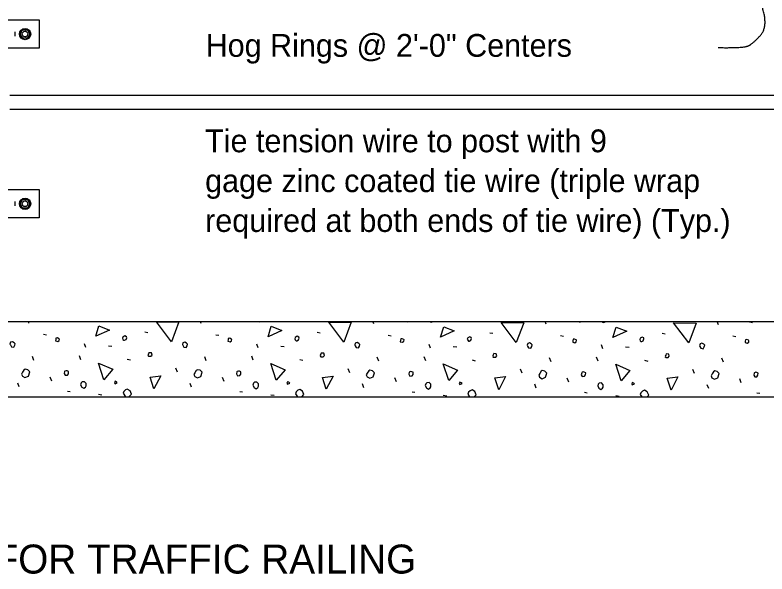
# Model space of a CAD drawing. Extents: x 0 to 72.1, y -7 to 30.
# Drawn here: x 12.41 to 19.06, y 13.96 to 18.9 of the extents above; entities that cross this region are included whole.
import ezdxf

# ---------------------------------------------------------------- set-up
doc = ezdxf.new("R2010")
doc.units = 0
for name, color, linetype in [('AdhocPoint_dp', 7, 'Continuous'), ('Border', 7, 'Continuous'), ('PlotBorder_dp', 7, 'Continuous'), ('TextMisc', 7, 'Continuous'), ('TextStructures', 7, 'Continuous')]:
    doc.layers.add(name, color=color, linetype=linetype)

msp = doc.modelspace()

# ---------------------------------------------------------------- linework, layer by layer
at = {"layer": 'AdhocPoint_dp'}
for p, q in [((12.5379, 16.1758), (12.5327, 16.1899)), ((14.0617, 16.1723), (14.0552, 16.1899)), ((15.5855, 16.1687), (15.5777, 16.1899)), ((15.8807, 16.1899), (15.8878, 16.1882)), ((17.1093, 16.1652), (17.1002, 16.1899)), ((17.3904, 16.1899), (17.4116, 16.1846)), ((18.6332, 16.1617), (18.6227, 16.1899)), ((18.9072, 16.1882), (18.9354, 16.1811)), ((13.5632, 16.098), (13.5897, 16.0927)), ((15.087, 16.0945), (15.1135, 16.0892)), ((16.6108, 16.0909), (16.6373, 16.0856)), ((18.1346, 16.0874), (18.1612, 16.0821)), ((12.6652, 16.0768), (12.6917, 16.0715)), ((14.189, 16.0733), (14.2155, 16.068)), ((15.7128, 16.0697), (15.7393, 16.0644)), ((17.2366, 16.0662), (17.2631, 16.0609)), ((18.7604, 16.0627), (18.787, 16.0574)), ((13.0399, 15.9601), (13.0276, 15.9937)), ((13.2397, 15.976), (13.2715, 15.9725)), ((14.5638, 15.9566), (14.5514, 15.9902)), ((14.7635, 15.9725), (14.7953, 15.969)), ((16.0876, 15.9531), (16.0752, 15.9866)), ((16.2873, 15.969), (16.3191, 15.9654)), ((17.6114, 15.9495), (17.599, 15.9831)), ((17.8111, 15.9654), (17.843, 15.9619)), ((12.5821, 15.8452), (12.5679, 15.8806)), ((12.9975, 15.8505), (12.9834, 15.8859)), ((13.4076, 15.8576), (13.4359, 15.8505)), ((14.1059, 15.8417), (14.0918, 15.877)), ((14.5213, 15.847), (14.5072, 15.8823)), ((14.9315, 15.8541), (14.9597, 15.847)), ((15.6297, 15.8381), (15.6156, 15.8735)), ((16.0451, 15.8435), (16.031, 15.8788)), ((16.4553, 15.8505), (16.4835, 15.8435)), ((17.1535, 15.8346), (17.1394, 15.87)), ((17.569, 15.8399), (17.5548, 15.8753)), ((17.9791, 15.847), (18.0074, 15.8399)), ((18.6773, 15.8311), (18.6632, 15.8664)), ((13.8496, 15.7409), (13.8354, 15.7763)), ((15.3734, 15.7374), (15.3592, 15.7727)), ((16.8972, 15.7339), (16.8831, 15.7692)), ((18.421, 15.7303), (18.4069, 15.7657)), ((12.7394, 15.6631), (12.7253, 15.6985)), ((14.2632, 15.6596), (14.2491, 15.695)), ((15.787, 15.6561), (15.7729, 15.6914)), ((17.3109, 15.6525), (17.2967, 15.6879)), ((12.4513, 15.6119), (12.4389, 15.6455)), ((13.9751, 15.6083), (13.9627, 15.6419)), ((15.4989, 15.6048), (15.4865, 15.6384)), ((17.0227, 15.6013), (17.0103, 15.6349)), ((18.5465, 15.5977), (18.5342, 15.6313)), ((18.8347, 15.649), (18.8205, 15.6844)), ((12.8773, 15.5748), (12.9021, 15.5712)), ((14.4011, 15.5712), (14.4259, 15.5677)), ((15.9249, 15.5677), (15.9497, 15.5641)), ((17.4488, 15.5641), (17.4735, 15.5606)), ((18.9726, 15.5606), (18.9973, 15.5571)), ((13.1531, 15.5465), (13.1831, 15.5412)), ((14.6769, 15.5429), (14.7069, 15.5376)), ((16.2007, 15.5394), (16.2308, 15.5341)), ((17.7245, 15.5359), (17.7546, 15.5306))]:
    msp.add_line(p, q, dxfattribs=at)
for points in [[(13.7983, 16.0114), (13.664, 16.1882), (13.8637, 16.1864), (13.7983, 16.0114)], [(14.5602, 16.1899), (14.5726, 16.1882), (14.5767, 16.1899)], [(15.3221, 16.0079), (15.1878, 16.1846), (15.3875, 16.1829), (15.3221, 16.0079)], [(16.0805, 16.1899), (16.084, 16.1864)], [(16.084, 16.1864), (16.0964, 16.1846), (16.1088, 16.1899)], [(16.8459, 16.0043), (16.7116, 16.1811), (16.9113, 16.1793), (16.8459, 16.0043)], [(17.6008, 16.1899), (17.6078, 16.1829)], [(17.6078, 16.1829), (17.6202, 16.1811), (17.6326, 16.1864), (17.6338, 16.1899)], [(18.3698, 16.0008), (18.2354, 16.1776), (18.4352, 16.1758), (18.3698, 16.0008)], [(13.1283, 16.0591), (13.1566, 16.151), (13.2503, 16.1139), (13.1283, 16.0591)], [(14.6521, 16.0556), (14.6804, 16.1475), (14.7741, 16.1104), (14.6521, 16.0556)], [(16.176, 16.052), (16.2042, 16.144), (16.2979, 16.1068), (16.176, 16.052)], [(17.6998, 16.0485), (17.7281, 16.1404), (17.8217, 16.1033), (17.6998, 16.0485)], [(12.773, 16.0185), (12.7925, 16.0132), (12.8048, 16.022), (12.8066, 16.0344), (12.8031, 16.0379), (12.7889, 16.045), (12.7765, 16.0432), (12.7748, 16.0308), (12.773, 16.0185)], [(13.3758, 16.0238), (13.3829, 16.0238), (13.397, 16.0308), (13.4023, 16.0467), (13.4006, 16.0556), (13.3864, 16.0627), (13.3687, 16.052), (13.3652, 16.0414), (13.3687, 16.0308), (13.3758, 16.0238)], [(14.2968, 16.0149), (14.3163, 16.0096), (14.3286, 16.0185), (14.3304, 16.0308), (14.3269, 16.0344), (14.3127, 16.0414), (14.3004, 16.0397), (14.2986, 16.0273), (14.2968, 16.0149)], [(14.8996, 16.0202), (14.9067, 16.0202), (14.9208, 16.0273), (14.9261, 16.0432), (14.9244, 16.052), (14.9102, 16.0591), (14.8926, 16.0485), (14.889, 16.0379), (14.8926, 16.0273), (14.8996, 16.0202)], [(15.8206, 16.0114), (15.8401, 16.0061), (15.8525, 16.0149), (15.8542, 16.0273), (15.8507, 16.0308), (15.8365, 16.0379), (15.8242, 16.0361), (15.8224, 16.0238), (15.8206, 16.0114)], [(16.4234, 16.0167), (16.4305, 16.0167), (16.4447, 16.0238), (16.45, 16.0397), (16.4482, 16.0485), (16.4341, 16.0556), (16.4164, 16.045), (16.4128, 16.0344), (16.4164, 16.0238), (16.4234, 16.0167)], [(17.3445, 16.0079), (17.3639, 16.0026), (17.3763, 16.0114), (17.378, 16.0238), (17.3745, 16.0273), (17.3604, 16.0344), (17.348, 16.0326), (17.3462, 16.0202), (17.3445, 16.0079)], [(17.9473, 16.0132), (17.9543, 16.0132), (17.9685, 16.0202), (17.9738, 16.0361), (17.972, 16.045), (17.9579, 16.052), (17.9402, 16.0414), (17.9367, 16.0308), (17.9402, 16.0202), (17.9473, 16.0132)], [(18.8683, 16.0043), (18.8877, 15.999), (18.9001, 16.0079), (18.9019, 16.0202), (18.8983, 16.0238), (18.8842, 16.0308), (18.8718, 16.0291), (18.87, 16.0167), (18.8683, 16.0043)], [(12.3735, 15.9831), (12.3823, 15.9672), (12.4035, 15.9637), (12.4124, 15.9796), (12.4159, 15.9937), (12.4071, 16.0026), (12.3912, 16.0114), (12.3753, 16.0061), (12.37, 15.9902), (12.3735, 15.9831)], [(13.8973, 15.9796), (13.9061, 15.9637), (13.9274, 15.9601), (13.9362, 15.976), (13.9397, 15.9902), (13.9309, 15.999), (13.915, 16.0079), (13.8991, 16.0026), (13.8938, 15.9866), (13.8973, 15.9796)], [(15.4211, 15.976), (15.43, 15.9601), (15.4512, 15.9566), (15.46, 15.9725), (15.4635, 15.9866), (15.4547, 15.9955), (15.4388, 16.0043), (15.4229, 15.999), (15.4176, 15.9831), (15.4211, 15.976)], [(16.9449, 15.9725), (16.9538, 15.9566), (16.975, 15.9531), (16.9838, 15.969), (16.9874, 15.9831), (16.9785, 15.9919), (16.9626, 16.0008), (16.9467, 15.9955), (16.9414, 15.9796), (16.9449, 15.9725)], [(18.4688, 15.969), (18.4776, 15.9531), (18.4988, 15.9495), (18.5076, 15.9654), (18.5112, 15.9796), (18.5023, 15.9884), (18.4864, 15.9972), (18.4705, 15.9919), (18.4652, 15.976), (18.4688, 15.969)], [(13.595, 15.8823), (13.6162, 15.8823), (13.6268, 15.8929), (13.6215, 15.9124), (13.5986, 15.9142), (13.595, 15.9036), (13.5897, 15.8947), (13.595, 15.8823), (13.5915, 15.8859)], [(15.1188, 15.8788), (15.14, 15.8788), (15.1507, 15.8894), (15.1454, 15.9089), (15.1224, 15.9106), (15.1188, 15.9), (15.1135, 15.8912), (15.1188, 15.8788), (15.1153, 15.8823)], [(16.6426, 15.8753), (16.6639, 15.8753), (16.6745, 15.8859), (16.6692, 15.9053), (16.6462, 15.9071), (16.6426, 15.8965), (16.6373, 15.8876), (16.6426, 15.8753), (16.6391, 15.8788)], [(18.1665, 15.8717), (18.1877, 15.8717), (18.1983, 15.8823), (18.193, 15.9018), (18.17, 15.9036), (18.1665, 15.8929), (18.1612, 15.8841), (18.1665, 15.8717), (18.1629, 15.8753)], [(13.2008, 15.6755), (13.1531, 15.8222), (13.2786, 15.7674), (13.2008, 15.6755)], [(12.4796, 15.7073), (12.5025, 15.695), (12.5326, 15.7073), (12.545, 15.7445), (12.5273, 15.7621), (12.5043, 15.7674), (12.4937, 15.7604), (12.4813, 15.7409), (12.4725, 15.725), (12.4796, 15.7073)], [(12.849, 15.7303), (12.8579, 15.7144), (12.8773, 15.7162), (12.8861, 15.7285), (12.8879, 15.748), (12.8755, 15.7533), (12.8667, 15.7551), (12.8561, 15.7515), (12.8526, 15.748), (12.849, 15.7303)], [(14.0034, 15.7038), (14.0264, 15.6914), (14.0564, 15.7038), (14.0688, 15.7409), (14.0511, 15.7586), (14.0281, 15.7639), (14.0175, 15.7568), (14.0051, 15.7374), (13.9963, 15.7215), (14.0034, 15.7038)], [(14.7246, 15.672), (14.6769, 15.8187), (14.8024, 15.7639), (14.7246, 15.672)], [(15.5272, 15.7003), (15.5502, 15.6879), (15.5802, 15.7003), (15.5926, 15.7374), (15.5749, 15.7551), (15.5519, 15.7604), (15.5413, 15.7533), (15.529, 15.7339), (15.5201, 15.7179), (15.5272, 15.7003)], [(16.2484, 15.6684), (16.2007, 15.8152), (16.3262, 15.7604), (16.2484, 15.6684)], [(17.051, 15.6967), (17.074, 15.6844), (17.104, 15.6967), (17.1164, 15.7339), (17.0987, 15.7515), (17.0758, 15.7568), (17.0651, 15.7498), (17.0528, 15.7303), (17.0439, 15.7144), (17.051, 15.6967)], [(17.7723, 15.6649), (17.7245, 15.8116), (17.85, 15.7568), (17.7723, 15.6649)], [(18.5748, 15.6932), (18.5978, 15.6808), (18.6279, 15.6932), (18.6402, 15.7303), (18.6225, 15.748), (18.5996, 15.7533), (18.589, 15.7462), (18.5766, 15.7268), (18.5677, 15.7109), (18.5748, 15.6932)], [(13.6427, 15.5942), (13.6092, 15.6985), (13.7029, 15.7109), (13.6427, 15.5942)], [(14.3728, 15.7268), (14.3817, 15.7109), (14.4011, 15.7126), (14.41, 15.725), (14.4117, 15.7445), (14.3994, 15.7498), (14.3905, 15.7515), (14.3799, 15.748), (14.3764, 15.7445), (14.3728, 15.7268)], [(15.1666, 15.5907), (15.133, 15.695), (15.2267, 15.7073), (15.1666, 15.5907)], [(15.8967, 15.7232), (15.9055, 15.7073), (15.9249, 15.7091), (15.9338, 15.7215), (15.9355, 15.7409), (15.9232, 15.7462), (15.9143, 15.748), (15.9037, 15.7445), (15.9002, 15.7409), (15.8967, 15.7232)], [(16.6904, 15.5871), (16.6568, 15.6914), (16.7505, 15.7038), (16.6904, 15.5871)], [(17.4205, 15.7197), (17.4293, 15.7038), (17.4488, 15.7056), (17.4576, 15.7179), (17.4594, 15.7374), (17.447, 15.7427), (17.4381, 15.7445), (17.4275, 15.7409), (17.424, 15.7374), (17.4205, 15.7197)], [(18.2142, 15.5836), (18.1806, 15.6879), (18.2743, 15.7003), (18.2142, 15.5836)], [(18.9443, 15.7162), (18.9531, 15.7003), (18.9726, 15.702), (18.9814, 15.7144), (18.9832, 15.7339), (18.9708, 15.7392), (18.962, 15.7409), (18.9514, 15.7374), (18.9478, 15.7339), (18.9443, 15.7162)], [(12.994, 15.6313), (13.0046, 15.6101), (13.0223, 15.5995), (13.0364, 15.6101), (13.0435, 15.6207), (13.0435, 15.6419), (13.0276, 15.6578), (13.0081, 15.6561), (12.9993, 15.6472), (12.994, 15.6313)], [(13.2998, 15.6402), (13.3192, 15.649), (13.3122, 15.6561), (13.2998, 15.6614), (13.2945, 15.649), (13.2998, 15.6402)], [(14.5178, 15.6278), (14.5284, 15.6066), (14.5461, 15.596), (14.5602, 15.6066), (14.5673, 15.6172), (14.5673, 15.6384), (14.5514, 15.6543), (14.5319, 15.6525), (14.5231, 15.6437), (14.5178, 15.6278)], [(14.8236, 15.6366), (14.8431, 15.6455), (14.836, 15.6525), (14.8236, 15.6578), (14.8183, 15.6455), (14.8236, 15.6366)], [(16.0416, 15.6242), (16.0522, 15.603), (16.0699, 15.5924), (16.084, 15.603), (16.0911, 15.6136), (16.0911, 15.6349), (16.0752, 15.6508), (16.0558, 15.649), (16.0469, 15.6402), (16.0416, 15.6242)], [(16.3474, 15.6331), (16.3669, 15.6419), (16.3598, 15.649), (16.3474, 15.6543), (16.3421, 15.6419), (16.3474, 15.6331)], [(17.5654, 15.6207), (17.576, 15.5995), (17.5937, 15.5889), (17.6078, 15.5995), (17.6149, 15.6101), (17.6149, 15.6313), (17.599, 15.6472), (17.5796, 15.6455), (17.5707, 15.6366), (17.5654, 15.6207)], [(17.8712, 15.6296), (17.8907, 15.6384), (17.8836, 15.6455), (17.8712, 15.6508), (17.8659, 15.6384), (17.8712, 15.6296)], [(13.4198, 15.5233), (13.4253, 15.5288), (13.4448, 15.5482), (13.4324, 15.5783), (13.4076, 15.5924), (13.39, 15.5854), (13.3758, 15.5712), (13.3705, 15.5553)], [(13.3705, 15.5553), (13.3903, 15.5233)], [(14.9471, 15.5233), (14.9491, 15.5253), (14.9686, 15.5447), (14.9562, 15.5748), (14.9315, 15.5889), (14.9138, 15.5818), (14.8996, 15.5677), (14.8943, 15.5518)], [(16.4745, 15.5233), (16.4924, 15.5412), (16.48, 15.5712), (16.4553, 15.5854), (16.4376, 15.5783), (16.4234, 15.5641), (16.4181, 15.5482)], [(18.0018, 15.5233), (18.0162, 15.5376), (18.0038, 15.5677), (17.9791, 15.5818), (17.9614, 15.5748), (17.9473, 15.5606), (17.942, 15.5447)], [(14.8943, 15.5518), (14.912, 15.5233)], [(16.4181, 15.5482), (16.4336, 15.5233)], [(17.942, 15.5447), (17.9552, 15.5233)]]:
    msp.add_lwpolyline(points, dxfattribs=at)
at = {"layer": 'Border'}
msp.add_open_spline([(18.6319, 18.6097), (18.8548, 18.6061), (18.9397, 18.6451), (19.0705, 18.7938), (18.9856, 19.0912), (18.9432, 19.3566)], degree=2, dxfattribs=at)
at = {"layer": 'PlotBorder_dp'}
for p, q in [((11.8163, 18.8548), (12.6282, 18.8548)), ((12.6282, 18.8548), (12.6282, 18.6048)), ((12.415, 18.7104), (12.415, 18.7493)), ((12.6282, 18.6048), (11.8163, 18.6048)), ((11.8163, 17.3548), (12.6282, 17.3548)), ((12.6282, 17.3548), (12.6282, 17.1048)), ((12.415, 17.2104), (12.415, 17.2493)), ((12.6282, 17.1048), (11.8163, 17.1048))]:
    msp.add_line(p, q, dxfattribs=at)
for points in [[(12.4816, 18.7674), (12.5249, 18.7674), (12.5466, 18.7298), (12.5249, 18.6923), (12.4816, 18.6923), (12.4599, 18.7298)], [(12.4816, 17.2674), (12.5249, 17.2674), (12.5466, 17.2298), (12.5249, 17.1923), (12.4816, 17.1923), (12.4599, 17.2298)]]:
    msp.add_lwpolyline(points, close=True, dxfattribs=at)
for centre, radius in [((12.5032, 18.7298), 0.05), ((12.5032, 18.7298), 0.025), ((12.5032, 17.2298), 0.05), ((12.5032, 17.2298), 0.025)]:
    msp.add_circle(centre, radius, dxfattribs=at)
at = {"layer": 'TextMisc'}
for p, q in [((12.3681, 18.1899), (22.0764, 18.1899)), ((12.3681, 18.0649), (22.0764, 18.0649)), ((0.8353, 16.1899), (23.6092, 16.1899)), ((0.8353, 15.5233), (23.6092, 15.5233))]:
    msp.add_line(p, q, dxfattribs=at)

# ---------------------------------------------------------------- texts
at = {"layer": 'Border'}
for s, p in [('Tie tension wire to post with 9 ', (14.0954, 17.685)), ('gage zinc coated tie wire (triple wrap ', (14.0954, 17.333)), ('required at both ends of tie wire) (Typ.)', (14.0954, 16.981))]:
    msp.add_text(s, height=0.2016, dxfattribs=at).set_placement(p)
at = {"layer": 'TextStructures'}
for s, height, p in [('Hog Rings @ 2\'-0" Centers', 0.2016, (14.1001, 18.5285)), ('PULL POST ASSEMBLY DETAIL FOR TRAFFIC RAILING', 0.256001, (7.0209, 13.9629))]:
    msp.add_text(s, height=height, dxfattribs=at).set_placement(p)

doc.saveas('drawing.dxf')
